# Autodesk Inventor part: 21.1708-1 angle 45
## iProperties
Created: 2007-01
Part Number: 21.1708-1 angle 45
Document SubType Name: Modeling
Designer: Andy Moles
Material: Aluminum-6061
Density: 2.71 g/cm^3
Author: Andy Moles
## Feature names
1. Extrusion1
2. Extrusion2
3. Extrusion3
4. Extrusion4
5. Hole1
6. Hole2
7. Hole3
8. Extrusion5
9. Extrusion6
10. Extrusion7
11. Extrusion8
12. Fillet1
